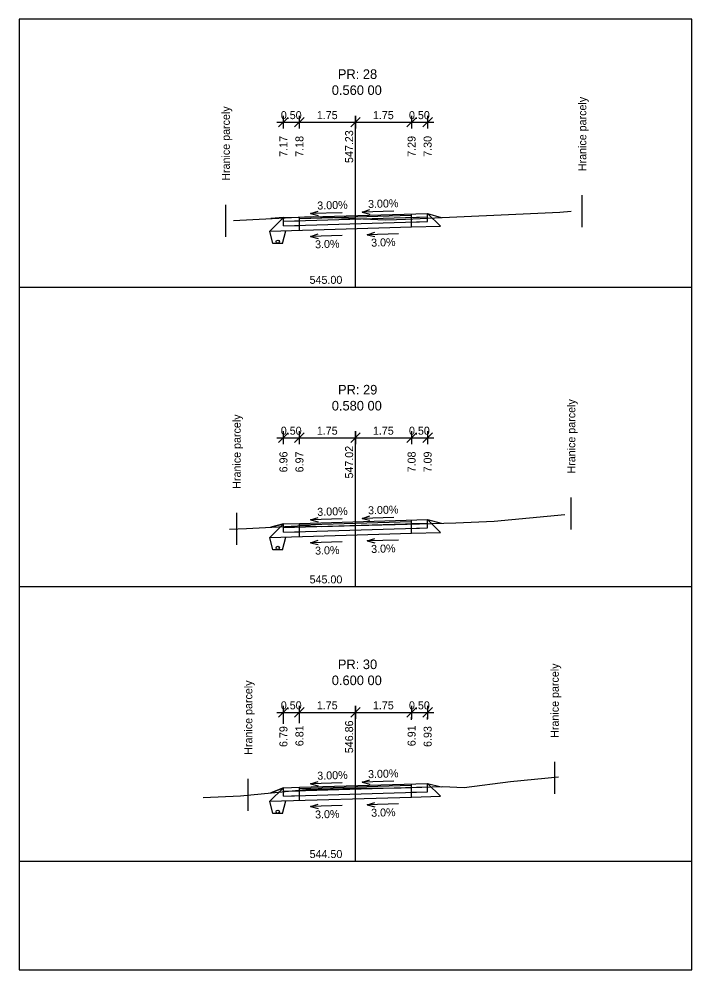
# Model space of a CAD drawing. Extents: x -603737 to -603383, y -1112154 to -1112124.
# Drawn here: x -603479.83 to -603458.83, y -1112153.84 to -1112124.14 of the extents above; entities that cross this region are included whole.
import ezdxf

# ---------------------------------------------------------------- set-up
doc = ezdxf.new("R2010")
doc.units = 0
for name, color, linetype in [('_křivky z hran', 7, 'Continuous'), ('_netisk', 7, 'Continuous'), ('C3D_Podsestava-Popis', 7, 'Continuous'), ('C3D_PP-Popisek', 7, 'Continuous'), ('C3D_PR', 7, 'Continuous'), ('C3D_ZPR', 7, 'Continuous'), ('Default', 7, 'Continuous'), ('konstrukce', 7, 'Continuous')]:
    doc.layers.add(name, color=color, linetype=linetype)

# ---------------------------------------------------------------- blocks, each defined once
blk = doc.blocks.new('_Oblique')
at = {"layer": 'Default'}
blk.add_line((-0.5, -0.5), (0.5, 0.5), dxfattribs=at)
blk = doc.blocks.new('AeccTickLine')
at = {"layer": 'Default'}
blk.add_line((0, 1), (0, -1), dxfattribs=at)

msp = doc.modelspace()

# ---------------------------------------------------------------- linework, layer by layer
at = {"layer": '_netisk'}
msp.add_lwpolyline([(-603479.831, -1112153.84), (-603458.831, -1112153.84), (-603458.831, -1112124.14), (-603479.831, -1112124.14)], close=True, dxfattribs=at)
at = {"layer": 'C3D_Podsestava-Popis'}
for p, q in [((-603471.781, -1112127.361), (-603469.331, -1112127.361)), ((-603469.331, -1112127.361), (-603466.881, -1112127.361)), ((-603469.331, -1112128.276), (-603469.331, -1112127.511)), ((-603471.781, -1112137.217), (-603469.331, -1112137.217)), ((-603469.331, -1112137.217), (-603466.881, -1112137.217)), ((-603469.331, -1112137.843), (-603469.331, -1112137.367)), ((-603471.781, -1112145.794), (-603469.331, -1112145.794)), ((-603469.331, -1112145.794), (-603466.881, -1112145.794)), ((-603471.581, -1112146.15), (-603471.581, -1112145.944)), ((-603471.081, -1112146.135), (-603471.081, -1112145.944)), ((-603469.331, -1112146.083), (-603469.331, -1112145.944)), ((-603467.581, -1112146.03), (-603467.581, -1112145.944)), ((-603467.081, -1112146.015), (-603467.081, -1112145.944))]:
    msp.add_line(p, q, dxfattribs=at)
at = {"layer": 'C3D_PP-Popisek'}
for p, q in [((-603470.734, -1112130.218), (-603470.497, -1112130.143)), ((-603469.122, -1112130.17), (-603468.886, -1112130.094)), ((-603468.139, -1112130.14), (-603469.122, -1112130.17)), ((-603469.75, -1112130.189), (-603470.734, -1112130.218)), ((-603470.734, -1112130.218), (-603470.493, -1112130.279)), ((-603469.122, -1112130.17), (-603468.882, -1112130.231)), ((-603470.734, -1112130.929), (-603470.497, -1112130.853)), ((-603469.75, -1112130.899), (-603470.734, -1112130.929)), ((-603470.734, -1112130.929), (-603470.493, -1112130.99)), ((-603468.969, -1112130.876), (-603468.732, -1112130.8)), ((-603467.985, -1112130.846), (-603468.969, -1112130.876)), ((-603468.969, -1112130.876), (-603468.728, -1112130.937)), ((-603469.122, -1112139.736), (-603468.886, -1112139.661)), ((-603470.734, -1112139.785), (-603470.497, -1112139.709)), ((-603469.75, -1112139.755), (-603470.734, -1112139.785)), ((-603470.734, -1112139.785), (-603470.493, -1112139.846)), ((-603468.139, -1112139.707), (-603469.122, -1112139.736)), ((-603469.122, -1112139.736), (-603468.882, -1112139.797)), ((-603470.734, -1112140.495), (-603470.497, -1112140.419)), ((-603469.75, -1112140.465), (-603470.734, -1112140.495)), ((-603470.734, -1112140.495), (-603470.493, -1112140.556)), ((-603468.969, -1112140.442), (-603468.732, -1112140.366)), ((-603467.985, -1112140.412), (-603468.969, -1112140.442)), ((-603468.969, -1112140.442), (-603468.728, -1112140.503)), ((-603470.734, -1112148.025), (-603470.497, -1112147.949)), ((-603469.122, -1112147.976), (-603468.886, -1112147.901)), ((-603468.139, -1112147.947), (-603469.122, -1112147.976)), ((-603469.122, -1112147.976), (-603468.882, -1112148.037)), ((-603469.75, -1112147.995), (-603470.734, -1112148.025)), ((-603470.734, -1112148.025), (-603470.493, -1112148.086)), ((-603470.734, -1112148.735), (-603470.497, -1112148.659)), ((-603469.75, -1112148.705), (-603470.734, -1112148.735)), ((-603470.734, -1112148.735), (-603470.493, -1112148.796)), ((-603468.969, -1112148.682), (-603468.732, -1112148.607)), ((-603467.985, -1112148.652), (-603468.969, -1112148.682)), ((-603468.969, -1112148.682), (-603468.728, -1112148.743))]:
    msp.add_line(p, q, dxfattribs=at)
at = {"layer": 'C3D_PR'}
for points in [[(-603473.143, -1112130.435), (-603470.923, -1112130.32), (-603470.644, -1112130.306), (-603469.331, -1112130.367), (-603468.4, -1112130.411), (-603468.052, -1112130.402), (-603467.767, -1112130.394), (-603462.954, -1112130.176), (-603462.604, -1112130.144)], [(-603473.258, -1112140.077), (-603472.73, -1112140.05), (-603470.939, -1112139.962), (-603470.399, -1112139.987), (-603469.331, -1112139.961), (-603468.09, -1112139.932), (-603466.2, -1112139.875), (-603465.008, -1112139.822), (-603462.803, -1112139.618)], [(-603474.087, -1112148.458), (-603472.917, -1112148.4), (-603470.878, -1112148.2), (-603469.346, -1112148.164), (-603469.331, -1112148.164), (-603467.908, -1112148.153), (-603466.615, -1112148.114), (-603465.942, -1112148.138), (-603464.494, -1112147.952), (-603462.991, -1112147.813)]]:
    msp.add_lwpolyline(points, dxfattribs=at)
at = {"layer": 'C3D_ZPR'}
for p, q in [((-603469.331, -1112132.511), (-603469.331, -1112127.511)), ((-603462.253, -1112130.643), (-603462.253, -1112129.643)), ((-603473.377, -1112130.94), (-603473.377, -1112129.94)), ((-603472.003, -1112130.767), (-603471.581, -1112130.344)), ((-603471.581, -1112130.344), (-603471.976, -1112130.374)), ((-603471.976, -1112130.374), (-603471.581, -1112130.344)), ((-603471.581, -1112130.454), (-603467.081, -1112130.319)), ((-603471.581, -1112130.344), (-603471.081, -1112130.329)), ((-603471.581, -1112130.604), (-603471.581, -1112130.344)), ((-603471.581, -1112130.604), (-603471.581, -1112130.344)), ((-603471.581, -1112130.454), (-603471.081, -1112130.439)), ((-603471.081, -1112130.329), (-603467.081, -1112130.209)), ((-603471.081, -1112130.369), (-603467.581, -1112130.264)), ((-603471.081, -1112130.739), (-603471.081, -1112130.329)), ((-603471.081, -1112130.439), (-603471.081, -1112130.369)), ((-603467.581, -1112130.264), (-603467.581, -1112130.224)), ((-603467.581, -1112130.634), (-603467.581, -1112130.224)), ((-603467.581, -1112130.334), (-603467.081, -1112130.319)), ((-603467.581, -1112130.484), (-603467.581, -1112130.334)), ((-603467.081, -1112130.469), (-603467.081, -1112130.209)), ((-603467.081, -1112130.469), (-603467.081, -1112130.209)), ((-603467.081, -1112130.209), (-603466.683, -1112130.607)), ((-603467.081, -1112130.209), (-603466.656, -1112130.343)), ((-603467.081, -1112130.209), (-603466.656, -1112130.343)), ((-603472.003, -1112130.767), (-603467.581, -1112130.634)), ((-603471.581, -1112130.604), (-603467.081, -1112130.469)), ((-603471.581, -1112130.604), (-603471.081, -1112130.589)), ((-603471.081, -1112130.739), (-603471.081, -1112130.589)), ((-603467.581, -1112130.484), (-603467.081, -1112130.469)), ((-603467.581, -1112130.634), (-603466.683, -1112130.607)), ((-603479.831, -1112132.511), (-603458.831, -1112132.511)), ((-603469.331, -1112141.867), (-603469.331, -1112137.367)), ((-603462.597, -1112140.086), (-603462.597, -1112139.086)), ((-603473.038, -1112140.562), (-603473.038, -1112139.562)), ((-603472.003, -1112140.333), (-603471.581, -1112139.91)), ((-603471.581, -1112139.91), (-603471.976, -1112140.013)), ((-603471.976, -1112140.013), (-603471.581, -1112139.91)), ((-603471.581, -1112140.02), (-603467.081, -1112139.885)), ((-603471.581, -1112139.91), (-603471.081, -1112139.895)), ((-603471.581, -1112140.17), (-603471.581, -1112139.91)), ((-603471.581, -1112140.17), (-603471.581, -1112139.91)), ((-603471.081, -1112139.895), (-603467.081, -1112139.775)), ((-603471.081, -1112139.935), (-603467.581, -1112139.83)), ((-603471.081, -1112140.305), (-603471.081, -1112139.895)), ((-603471.081, -1112140.005), (-603471.081, -1112139.935)), ((-603467.581, -1112139.83), (-603467.581, -1112139.79)), ((-603467.581, -1112140.2), (-603467.581, -1112139.79)), ((-603467.581, -1112139.9), (-603467.081, -1112139.885)), ((-603467.581, -1112140.05), (-603467.581, -1112139.9)), ((-603467.081, -1112140.035), (-603467.081, -1112139.775)), ((-603467.081, -1112140.035), (-603467.081, -1112139.775)), ((-603467.081, -1112139.775), (-603466.683, -1112140.173)), ((-603467.081, -1112139.775), (-603466.656, -1112139.889)), ((-603467.081, -1112139.775), (-603466.656, -1112139.889)), ((-603472.003, -1112140.333), (-603467.581, -1112140.2)), ((-603471.581, -1112140.02), (-603471.081, -1112140.005)), ((-603471.581, -1112140.17), (-603467.081, -1112140.035)), ((-603471.581, -1112140.17), (-603471.081, -1112140.155)), ((-603471.081, -1112140.305), (-603471.081, -1112140.155)), ((-603467.581, -1112140.05), (-603467.081, -1112140.035)), ((-603467.581, -1112140.2), (-603466.683, -1112140.173)), ((-603479.831, -1112141.867), (-603458.831, -1112141.867)), ((-603469.331, -1112150.444), (-603469.331, -1112145.944)), ((-603463.112, -1112148.34), (-603463.112, -1112147.34)), ((-603472.676, -1112148.87), (-603472.676, -1112147.87)), ((-603472.003, -1112148.573), (-603471.581, -1112148.15)), ((-603471.581, -1112148.15), (-603471.976, -1112148.308)), ((-603471.976, -1112148.308), (-603471.581, -1112148.15)), ((-603471.581, -1112148.26), (-603467.081, -1112148.125)), ((-603471.581, -1112148.15), (-603471.081, -1112148.135)), ((-603471.581, -1112148.41), (-603471.581, -1112148.15)), ((-603471.581, -1112148.41), (-603471.581, -1112148.15)), ((-603471.581, -1112148.26), (-603471.081, -1112148.245)), ((-603471.581, -1112148.41), (-603467.081, -1112148.275)), ((-603471.081, -1112148.135), (-603467.081, -1112148.015)), ((-603471.081, -1112148.175), (-603467.581, -1112148.07)), ((-603471.081, -1112148.545), (-603471.081, -1112148.135)), ((-603471.081, -1112148.245), (-603471.081, -1112148.175)), ((-603467.581, -1112148.07), (-603467.581, -1112148.03)), ((-603467.581, -1112148.44), (-603467.581, -1112148.03)), ((-603467.581, -1112148.14), (-603467.081, -1112148.125)), ((-603467.581, -1112148.29), (-603467.581, -1112148.14)), ((-603467.581, -1112148.29), (-603467.081, -1112148.275)), ((-603467.081, -1112148.275), (-603467.081, -1112148.015)), ((-603467.081, -1112148.275), (-603467.081, -1112148.015)), ((-603467.081, -1112148.015), (-603466.683, -1112148.413)), ((-603467.081, -1112148.015), (-603466.656, -1112148.116)), ((-603467.081, -1112148.015), (-603466.656, -1112148.116)), ((-603472.003, -1112148.573), (-603467.581, -1112148.44)), ((-603471.581, -1112148.41), (-603471.081, -1112148.395)), ((-603471.081, -1112148.545), (-603471.081, -1112148.395)), ((-603467.581, -1112148.44), (-603466.683, -1112148.413)), ((-603479.831, -1112150.444), (-603458.831, -1112150.444))]:
    msp.add_line(p, q, dxfattribs=at)
at = {"layer": 'konstrukce'}
for p, q in [((-603471.607, -1112131.152), (-603471.507, -1112130.752)), ((-603471.907, -1112131.152), (-603472.003, -1112130.767)), ((-603471.607, -1112131.152), (-603471.907, -1112131.152)), ((-603471.907, -1112140.718), (-603472.003, -1112140.333)), ((-603471.607, -1112140.718), (-603471.507, -1112140.318)), ((-603471.607, -1112140.718), (-603471.907, -1112140.718)), ((-603471.907, -1112148.958), (-603472.003, -1112148.573)), ((-603471.607, -1112148.958), (-603471.507, -1112148.558)), ((-603471.607, -1112148.958), (-603471.907, -1112148.958))]:
    msp.add_line(p, q, dxfattribs=at)
for centre in [(-603471.757, -1112131.092), (-603471.757, -1112140.658), (-603471.757, -1112148.898)]:
    msp.add_circle(centre, 0.05, dxfattribs=at)

# ---------------------------------------------------------------- block references
at = {"layer": '_křivky z hran', "rotation": 180}
for name, p, xscale, yscale in [('AeccTickLine', (-603471.581, -1112127.361), 0.2, 0.20000000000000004), ('AeccTickLine', (-603471.081, -1112127.361), 0.2, 0.20000000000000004), ('AeccTickLine', (-603469.331, -1112127.361), 0.2, 0.20000000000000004), ('_Oblique', (-603471.581, -1112127.361), 0.3, 0.3), ('_Oblique', (-603471.081, -1112127.361), 0.3, 0.3), ('_Oblique', (-603469.331, -1112127.361), 0.3, 0.3), ('_Oblique', (-603471.581, -1112137.217), 0.3, 0.3), ('AeccTickLine', (-603471.581, -1112137.217), 0.2, 0.20000000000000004), ('_Oblique', (-603471.081, -1112137.217), 0.3, 0.3), ('AeccTickLine', (-603471.081, -1112137.217), 0.2, 0.20000000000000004), ('_Oblique', (-603469.331, -1112137.217), 0.3, 0.3), ('AeccTickLine', (-603469.331, -1112137.217), 0.2, 0.20000000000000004), ('AeccTickLine', (-603471.581, -1112145.794), 0.2, 0.20000000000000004), ('AeccTickLine', (-603471.081, -1112145.794), 0.2, 0.20000000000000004), ('AeccTickLine', (-603469.331, -1112145.794), 0.2, 0.20000000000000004), ('_Oblique', (-603471.581, -1112145.794), 0.3, 0.3), ('_Oblique', (-603471.081, -1112145.794), 0.3, 0.3), ('_Oblique', (-603469.331, -1112145.794), 0.3, 0.3)]:
    msp.add_blockref(name, p, dxfattribs=dict(at, xscale=xscale, yscale=yscale))
at = {"layer": '_křivky z hran'}
for name, p, xscale, yscale in [('AeccTickLine', (-603469.331, -1112127.361), 0.2, 0.20000000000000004), ('AeccTickLine', (-603467.581, -1112127.361), 0.2, 0.20000000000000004), ('AeccTickLine', (-603467.081, -1112127.361), 0.2, 0.20000000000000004), ('_Oblique', (-603469.331, -1112127.361), 0.3, 0.3), ('_Oblique', (-603467.581, -1112127.361), 0.3, 0.3), ('_Oblique', (-603467.081, -1112127.361), 0.3, 0.3), ('_Oblique', (-603469.331, -1112137.217), 0.3, 0.3), ('AeccTickLine', (-603469.331, -1112137.217), 0.2, 0.20000000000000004), ('_Oblique', (-603467.581, -1112137.217), 0.3, 0.3), ('AeccTickLine', (-603467.581, -1112137.217), 0.2, 0.20000000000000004), ('_Oblique', (-603467.081, -1112137.217), 0.3, 0.3), ('AeccTickLine', (-603467.081, -1112137.217), 0.2, 0.20000000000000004), ('AeccTickLine', (-603469.331, -1112145.794), 0.2, 0.20000000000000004), ('AeccTickLine', (-603467.581, -1112145.794), 0.2, 0.20000000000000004), ('AeccTickLine', (-603467.081, -1112145.794), 0.2, 0.20000000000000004), ('_Oblique', (-603469.331, -1112145.794), 0.3, 0.3), ('_Oblique', (-603467.581, -1112145.794), 0.3, 0.3), ('_Oblique', (-603467.081, -1112145.794), 0.3, 0.3)]:
    msp.add_blockref(name, p, dxfattribs=dict(at, xscale=xscale, yscale=yscale))

# ---------------------------------------------------------------- texts
at = {"layer": 'C3D_Podsestava-Popis'}
for s, rotation, p in [('0.50', 360, (-603471.662, -1112127.267)), ('1.75', 360, (-603470.538, -1112127.267)), ('1.75', 360, (-603470.538, -1112127.267)), ('1.75', 360, (-603468.788, -1112127.267)), ('1.75', 360, (-603468.788, -1112127.267)), ('0.50', 360, (-603467.662, -1112127.267)), ('547.23', 90, (-603469.405, -1112128.637)), ('7.17', 90, (-603471.455, -1112128.443)), ('7.17', 90, (-603471.455, -1112128.443)), ('7.18', 90, (-603470.955, -1112128.443)), ('7.29', 90, (-603467.455, -1112128.443)), ('7.30', 90, (-603466.955, -1112128.443)), ('7.30', 90, (-603466.955, -1112128.443)), ('3.00%', 1.7184, (-603470.52, -1112130.092)), ('3.00%', 1.7184, (-603468.936, -1112130.044)), ('3.0%', 1.7184, (-603470.589, -1112131.303)), ('3.0%', 1.7184, (-603468.839, -1112131.251)), ('0.50', 360, (-603471.662, -1112137.123)), ('1.75', 360, (-603470.538, -1112137.123)), ('1.75', 360, (-603470.538, -1112137.123)), ('1.75', 360, (-603468.788, -1112137.123)), ('1.75', 360, (-603468.788, -1112137.123)), ('0.50', 360, (-603467.662, -1112137.123)), ('547.02', 90, (-603469.405, -1112138.492)), ('6.96', 90, (-603471.455, -1112138.299)), ('6.96', 90, (-603471.455, -1112138.299)), ('6.97', 90, (-603470.955, -1112138.299)), ('7.08', 90, (-603467.455, -1112138.299)), ('7.09', 90, (-603466.955, -1112138.299)), ('7.09', 90, (-603466.955, -1112138.299)), ('3.00%', 1.7184, (-603468.936, -1112139.61)), ('3.00%', 1.7184, (-603470.52, -1112139.659)), ('3.0%', 1.7184, (-603468.839, -1112140.817)), ('3.0%', 1.7184, (-603470.589, -1112140.87)), ('0.50', 360, (-603471.662, -1112145.7)), ('1.75', 360, (-603470.538, -1112145.7)), ('1.75', 360, (-603470.538, -1112145.7)), ('1.75', 360, (-603468.788, -1112145.7)), ('1.75', 360, (-603468.788, -1112145.7)), ('0.50', 360, (-603467.662, -1112145.7)), ('546.86', 90, (-603469.405, -1112147.07)), ('6.79', 90, (-603471.455, -1112146.876)), ('6.79', 90, (-603471.455, -1112146.876)), ('6.81', 90, (-603470.955, -1112146.851)), ('6.91', 90, (-603467.455, -1112146.851)), ('6.93', 90, (-603466.955, -1112146.875)), ('6.93', 90, (-603466.955, -1112146.875)), ('3.00%', 1.7184, (-603470.52, -1112147.899)), ('3.00%', 1.7184, (-603468.936, -1112147.85)), ('3.0%', 1.7184, (-603470.589, -1112149.11)), ('3.0%', 1.7184, (-603468.839, -1112149.057))]:
    msp.add_text(s, height=0.25, rotation=rotation, dxfattribs=at).set_placement(p)
at = {"layer": 'C3D_ZPR'}
for s, p in [('PR: 28', (-603469.881, -1112126.011)), ('0.560 00', (-603470.071, -1112126.511)), ('PR: 29', (-603469.876, -1112135.867)), ('0.580 00', (-603470.071, -1112136.367)), ('PR: 30', (-603469.881, -1112144.444)), ('0.600 00', (-603470.071, -1112144.944))]:
    msp.add_text(s, height=0.3, dxfattribs=at).set_placement(p)
for s, rotation, p in [('Hranice parcely', 90, (-603462.128, -1112128.893)), ('Hranice parcely', 90, (-603473.252, -1112129.19)), ('545.00', 360, (-603470.764, -1112132.411)), ('Hranice parcely', 90, (-603462.472, -1112138.336)), ('Hranice parcely', 90, (-603472.913, -1112138.812)), ('545.00', 360, (-603470.764, -1112141.767)), ('Hranice parcely', 90, (-603462.987, -1112146.59)), ('Hranice parcely', 90, (-603472.551, -1112147.12)), ('544.50', 360, (-603470.764, -1112150.344))]:
    msp.add_text(s, height=0.25, rotation=rotation, dxfattribs=at).set_placement(p)

doc.saveas('drawing.dxf')
